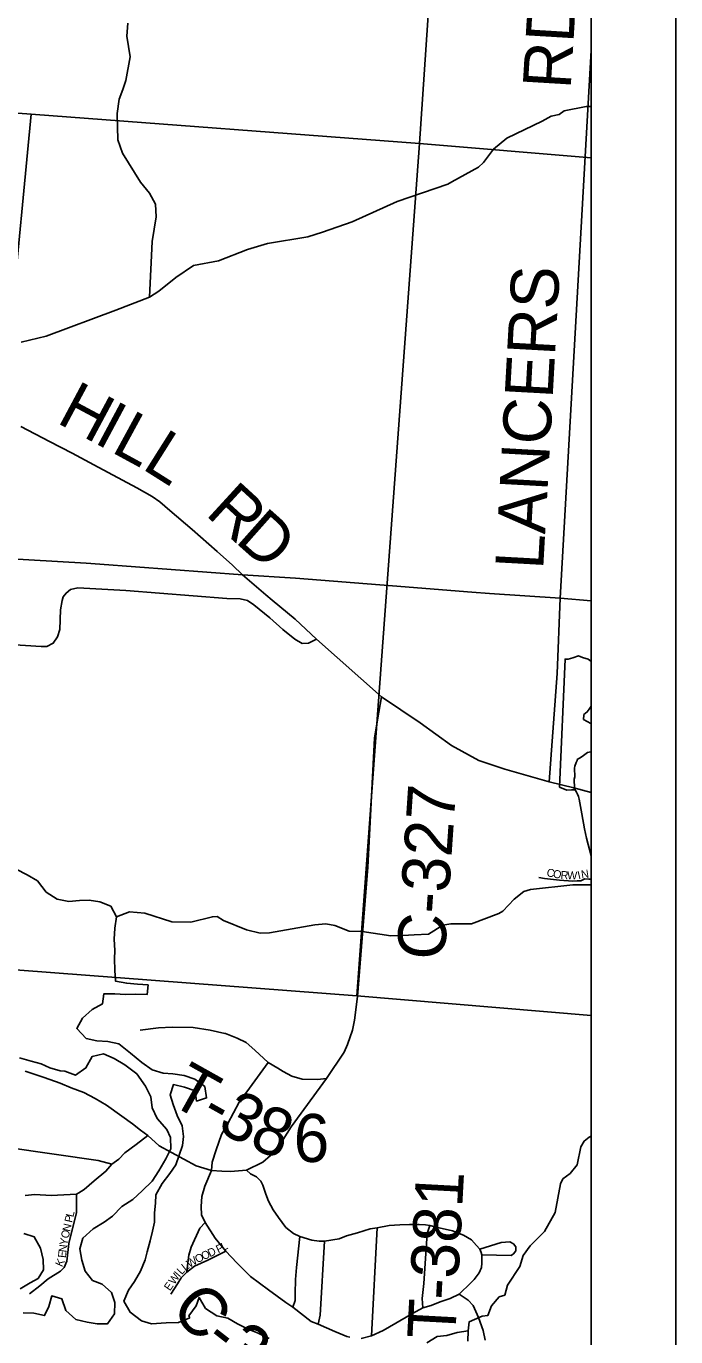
# Model space of a CAD drawing. Extents: x 0 to 40.4, y 0 to 22.
# Drawn here: x 8.731 to 9.5, y 15.17 to 16.72 of the extents above; entities that cross this region are included whole.
import ezdxf

# ---------------------------------------------------------------- set-up
doc = ezdxf.new("R2010")
doc.units = 0
for name, color, linetype in [('GM_X_County_Road', 7, 'Continuous'), ('GM_X_County_Road_Text', 7, 'Continuous'), ('GM_X_Interstate_Route', 7, 'Continuous'), ('GM_X_Major_Lake', 7, 'Continuous'), ('GM_X_Minor_Lake', 7, 'Continuous'), ('GM_X_Minor_River', 7, 'Continuous'), ('GM_X_Section', 7, 'Continuous'), ('GM_X_Township_Road', 7, 'Continuous'), ('GM_X_Township_Road_Text', 7, 'Continuous'), ('GM_X_Township_Subdivision', 7, 'Continuous'), ('GM_X_Township_Subdivision_Text', 7, 'Continuous'), ('SH_Data', 7, 'Continuous')]:
    doc.layers.add(name, color=color, linetype=linetype)

msp = doc.modelspace()

# ---------------------------------------------------------------- linework, layer by layer
at = {"layer": 'GM_X_County_Road'}
for points in [[(9.3501, 15.8263), (9.3597, 15.9545), (9.3632, 16.0434), (9.4, 16.6916)], [(8.725, 16.2467), (8.7589, 16.2289), (8.7858, 16.2152), (8.8114, 16.2014), (8.8624, 16.1742), (8.8803, 16.1638), (8.8894, 16.1574), (8.9013, 16.1472), (8.9275, 16.1249), (8.9571, 16.0988), (8.9755, 16.0824), (8.9871, 16.071), (9.0149, 16.0474), (9.0223, 16.0411), (9.0494, 16.0188), (9.0749, 15.9951), (9.1516, 15.9268), (9.1976, 15.8958), (9.2345, 15.869), (9.2671, 15.8514), (9.2977, 15.841), (9.3501, 15.8263), (9.3793, 15.819), (9.4, 15.8136)], [(9.1516, 15.9268), (9.147, 15.8996), (9.1436, 15.8778), (9.1356, 15.7253), (9.1233, 15.5721), (9.1197, 15.5443), (9.1173, 15.5324), (9.1114, 15.5153), (9.1076, 15.5061), (9.0865, 15.4753), (9.0448, 15.4181), (9.0307, 15.3953), (9.0208, 15.3841), (9.0205, 15.3839)], [(9.4, 15.7383), (9.3999, 15.7387), (9.3944, 15.7597), (9.3919, 15.7704), (9.3888, 15.7884), (9.3856, 15.8057), (9.3847, 15.8089), (9.3837, 15.8117), (9.3824, 15.8138), (9.3793, 15.819)], [(9.0205, 15.3839), (9.0114, 15.3762), (8.9919, 15.3667), (8.9731, 15.3652), (8.9629, 15.3654), (8.9506, 15.3662), (8.9324, 15.3717), (8.8886, 15.3954), (8.8754, 15.4076), (8.8667, 15.4141), (8.8571, 15.4215), (8.8445, 15.4307), (8.8262, 15.4434), (8.8129, 15.4515), (8.7996, 15.4585), (8.7845, 15.4641), (8.7714, 15.4695), (8.7525, 15.4765), (8.7302, 15.4837)], [(8.7302, 15.3367), (8.7415, 15.338), (8.761, 15.3368), (8.791, 15.3384), (8.7937, 15.3398), (8.7998, 15.3439), (8.8116, 15.3541), (8.8257, 15.3654), (8.8327, 15.3739), (8.841, 15.3798), (8.8482, 15.3871), (8.8614, 15.3969), (8.8754, 15.4076)], [(8.9506, 15.3662), (8.9426, 15.3478), (8.9391, 15.3354), (8.9382, 15.3236), (8.9388, 15.3137), (8.943, 15.3048), (8.9551, 15.2861), (8.9675, 15.2707), (8.9807, 15.2571), (8.9969, 15.241), (9.0181, 15.2249), (9.0385, 15.2101), (9.047, 15.2045), (9.0685, 15.1877), (9.0768, 15.1846), (9.0967, 15.1758), (9.1106, 15.1698), (9.1141, 15.1689)], [(9.1276, 15.1673), (9.1399, 15.1707), (9.1537, 15.177), (9.1886, 15.1972), (9.2007, 15.2037), (9.2106, 15.2066), (9.2212, 15.2108), (9.233, 15.2149), (9.2437, 15.2201), (9.2575, 15.2333), (9.2615, 15.2373), (9.2675, 15.2453), (9.2699, 15.2514), (9.2705, 15.2566), (9.2704, 15.2664), (9.2698, 15.2693), (9.2682, 15.2732), (9.2642, 15.2776), (9.2582, 15.2843), (9.2489, 15.2899), (9.2356, 15.2948), (9.2163, 15.2994), (9.2091, 15.3013), (9.204, 15.3021), (9.1963, 15.3022), (9.1849, 15.3023), (9.1733, 15.302), (9.161, 15.3011), (9.1465, 15.2985), (9.1382, 15.2971), (9.1234, 15.2927), (9.1103, 15.2888), (9.1018, 15.2855), (9.0842, 15.2828), (9.0779, 15.2828), (9.0692, 15.2837), (9.0551, 15.288), (9.0475, 15.2918), (9.0387, 15.2988), (9.0299, 15.3106), (9.0236, 15.3199), (9.0182, 15.33), (9.0148, 15.3382), (9.0113, 15.3491), (9.009, 15.3538), (9.0039, 15.3588), (8.9966, 15.3622), (8.9919, 15.3667)], [(9.2437, 15.2201), (9.2542, 15.213), (9.2604, 15.2065), (9.2665, 15.1924), (9.2719, 15.177), (9.2746, 15.1654)]]:
    msp.add_lwpolyline(points, dxfattribs=at)
at = {"layer": 'GM_X_Interstate_Route'}
for points in [[(7.7959, 16.068), (7.8971, 16.0785), (8.0522, 16.0948), (8.1652, 16.1082), (8.2508, 16.1101), (8.3578, 16.109), (8.7001, 16.0907), (8.8023, 16.0849), (8.8184, 16.0837)], [(8.8184, 16.0837), (8.9871, 16.071), (9.0501, 16.0671), (9.1647, 16.0579)], [(9.1647, 16.0579), (9.2585, 16.0504), (9.2796, 16.049)], [(9.2796, 16.049), (9.3632, 16.0434), (9.4, 16.0404)]]:
    msp.add_lwpolyline(points, dxfattribs=at)
at = {"layer": 'GM_X_Major_Lake'}
for points in [[(8.8756, 15.5859), (8.8628, 15.5868), (8.8503, 15.5879), (8.8371, 15.5903), (8.836, 15.6032), (8.8357, 15.6168), (8.8361, 15.6267), (8.8354, 15.64), (8.8362, 15.6532), (8.8382, 15.6665), (8.8314, 15.679), (8.8186, 15.684), (8.8057, 15.686), (8.7944, 15.6856), (8.7819, 15.6845), (8.7679, 15.6872), (8.7551, 15.6956), (8.7445, 15.7089), (8.7325, 15.7162), (8.7193, 15.7227)], [(8.9251, 15.1921), (8.9114, 15.1865), (8.8971, 15.1862), (8.8797, 15.1847), (8.8676, 15.1882), (8.8544, 15.1985), (8.8469, 15.2118), (8.8522, 15.2246), (8.8595, 15.2349), (8.8667, 15.247), (8.872, 15.2606), (8.8744, 15.2701), (8.8778, 15.2829), (8.8809, 15.2943), (8.8832, 15.3053), (8.8832, 15.3163), (8.8844, 15.3277), (8.8845, 15.3375), (8.8921, 15.3508), (8.9012, 15.3629), (8.9084, 15.3731), (8.9161, 15.3958), (8.9176, 15.4064), (8.9158, 15.4193), (8.9098, 15.4315), (8.9053, 15.4444), (8.9016, 15.4558), (8.9054, 15.4679), (8.9186, 15.4648), (8.9311, 15.4606), (8.9329, 15.4484), (8.9447, 15.4522), (8.9425, 15.4655), (8.9308, 15.4742), (8.9183, 15.4785), (8.9047, 15.4808), (8.8934, 15.4816), (8.8805, 15.4854), (8.8681, 15.4942), (8.8549, 15.5053), (8.8409, 15.5163), (8.8277, 15.519), (8.8149, 15.5198), (8.8024, 15.5225), (8.7911, 15.5343), (8.798, 15.5464), (8.8093, 15.5566), (8.8215, 15.5634), (8.823, 15.5752), (8.8363, 15.5755), (8.8487, 15.5747), (8.8608, 15.575), (8.8745, 15.5746), (8.8756, 15.5859)], [(8.7769, 15.4839), (8.7716, 15.4843), (8.7591, 15.4878), (8.749, 15.4924), (8.7372, 15.4955), (8.7233, 15.4997)], [(8.8686, 15.3421), (8.8804, 15.3538), (8.8884, 15.366), (8.8967, 15.38), (8.9025, 15.3921), (8.9021, 15.4053), (8.8976, 15.4148), (8.8863, 15.4278), (8.8803, 15.4403), (8.8789, 15.4536), (8.8725, 15.4661), (8.8624, 15.4806), (8.848, 15.4913), (8.8352, 15.4989), (8.8227, 15.5042), (8.8095, 15.5013), (8.8019, 15.4876), (8.7897, 15.479), (8.7769, 15.4839)], [(8.7277, 15.1978), (8.7402, 15.1974), (8.753, 15.1947), (8.758, 15.2053), (8.7615, 15.2178), (8.7735, 15.2143), (8.778, 15.2007), (8.7901, 15.19), (8.8033, 15.1869), (8.8154, 15.185), (8.8275, 15.1849), (8.8359, 15.1966), (8.8363, 15.2099), (8.8322, 15.2221), (8.8213, 15.2316), (8.8099, 15.2362), (8.8009, 15.2472), (8.7972, 15.2601), (8.7946, 15.2734), (8.7984, 15.2863), (8.8106, 15.2972), (8.8234, 15.3052), (8.8333, 15.3123), (8.8443, 15.3237), (8.8576, 15.3319), (8.8686, 15.3421)], [(8.7285, 15.2919), (8.7409, 15.2876), (8.7481, 15.2743), (8.7514, 15.2611), (8.7517, 15.2489), (8.7453, 15.2383), (8.7358, 15.2334), (8.724, 15.2263)], [(9.0188, 15.1675), (9.0059, 15.1736), (8.9939, 15.1786), (8.9814, 15.1847), (8.9697, 15.1916), (8.9569, 15.1943), (8.9433, 15.2031), (8.9358, 15.216), (8.9323, 15.2061), (8.9236, 15.1944), (8.9251, 15.1921)], [(9.254, 15.1643), (9.2544, 15.1764), (9.2411, 15.1746), (9.229, 15.1712), (9.2177, 15.1698), (9.2055, 15.1622)]]:
    msp.add_lwpolyline(points, dxfattribs=at)
at = {"layer": 'GM_X_Minor_Lake'}
for points in [[(9.4, 15.9687), (9.398, 15.9703), (9.3965, 15.9714), (9.3897, 15.9733), (9.3848, 15.9752), (9.3783, 15.973), (9.3727, 15.9715), (9.3689, 15.9715), (9.3625, 15.8198)], [(9.3907, 15.9001), (9.3911, 15.9051), (9.3911, 15.9058), (9.3952, 15.9089), (9.3975, 15.9123), (9.4, 15.9157)], [(9.4, 15.8949), (9.3994, 15.8952), (9.3907, 15.9001)], [(9.3625, 15.8198), (9.3712, 15.8164), (9.3765, 15.8167), (9.3799, 15.8167), (9.3803, 15.8186), (9.3799, 15.8292), (9.3807, 15.8319), (9.38, 15.8425), (9.3804, 15.8448), (9.3823, 15.849), (9.3834, 15.8516), (9.3834, 15.8524), (9.3879, 15.8554), (9.3906, 15.8573), (9.3955, 15.8607), (9.3993, 15.8618), (9.4, 15.8619)]]:
    msp.add_lwpolyline(points, dxfattribs=at)
at = {"layer": 'GM_X_Minor_River'}
for points in [[(8.8771, 16.3998), (8.8802, 16.4654), (8.8852, 16.4946), (8.8841, 16.5097), (8.8773, 16.5226), (8.8667, 16.5359), (8.8453, 16.5701), (8.8396, 16.586), (8.8389, 16.6171), (8.8412, 16.6338), (8.8458, 16.6455), (8.8492, 16.6562), (8.8542, 16.6842), (8.8504, 16.7085), (8.8516, 16.724)], [(8.7253, 16.3466), (8.7548, 16.3537), (8.8373, 16.3843), (8.8771, 16.3998), (8.8884, 16.4066), (8.9085, 16.4228), (8.9293, 16.4372), (8.9588, 16.4425), (8.9932, 16.4561), (9.0167, 16.4632), (9.0647, 16.4711), (9.0821, 16.4767), (9.117, 16.4888), (9.1703, 16.513), (9.2301, 16.5333), (9.235, 16.536), (9.2664, 16.5534), (9.2725, 16.559), (9.2842, 16.5749), (9.3001, 16.5878), (9.3418, 16.6078), (9.3527, 16.6139), (9.3618, 16.6157), (9.3679, 16.6203), (9.394, 16.6252), (9.4, 16.6252)], [(8.8382, 15.6665), (8.8537, 15.6725), (8.8715, 15.6706), (8.9036, 15.6606), (8.9263, 15.6602), (8.9516, 15.6666), (8.9573, 15.667), (8.9648, 15.662), (8.9921, 15.651), (9.0083, 15.6472), (9.0193, 15.6475), (9.073, 15.6569), (9.0858, 15.658), (9.0964, 15.6561), (9.1134, 15.6496), (9.1289, 15.6492), (9.1626, 15.6438), (9.1837, 15.6446), (9.1902, 15.6453), (9.2072, 15.646), (9.2242, 15.6566), (9.2337, 15.6581), (9.2582, 15.6581), (9.2904, 15.6705), (9.2953, 15.6732), (9.3086, 15.6872), (9.3203, 15.6963), (9.3279, 15.6989), (9.3782, 15.7041), (9.4, 15.7041)], [(9.2544, 15.1764), (9.2554, 15.1871), (9.271, 15.1939), (9.2774, 15.1946), (9.2819, 15.206), (9.291, 15.2166), (9.2975, 15.2189), (9.3009, 15.2306), (9.3153, 15.2526), (9.3195, 15.2655), (9.3278, 15.2772), (9.3369, 15.2863), (9.3445, 15.2942), (9.3574, 15.3166), (9.3635, 15.3503), (9.3662, 15.3564), (9.3749, 15.3628), (9.3832, 15.373), (9.3878, 15.3943), (9.3916, 15.4011), (9.3973, 15.4056), (9.4, 15.4069)]]:
    msp.add_lwpolyline(points, dxfattribs=at)
at = {"layer": 'GM_X_Section'}
for p, q in [((9.4, 16.5646), (9.4, 17.0997)), ((9.4, 15.5496), (9.4, 16.5646))]:
    msp.add_line(p, q, dxfattribs=at)
for points in [[(8.2373, 17.1912), (9.2326, 17.1127), (9.1966, 16.5816), (8.7372, 16.616), (8.202, 16.6562)], [(8.202, 16.6562), (8.7372, 16.616), (8.6406, 15.6095), (8.1289, 15.6484), (8.1953, 16.5941)], [(8.7372, 16.616), (9.1966, 16.5816), (9.1227, 15.573), (8.6406, 15.6095)]]:
    msp.add_lwpolyline(points, close=True, dxfattribs=at)
for points in [[(9.4, 17.0997), (9.2326, 17.1127), (9.1966, 16.5816), (9.4, 16.5646)], [(9.4, 16.5646), (9.1966, 16.5816), (9.1227, 15.573), (9.4, 15.5496)]]:
    msp.add_lwpolyline(points, dxfattribs=at)
at = {"layer": 'GM_X_Township_Road'}
for points in [[(9.0749, 15.9951), (9.0654, 15.9904), (9.058, 15.9898), (9.0492, 15.9948), (9.035, 16.0065), (9.0196, 16.0204), (9.0006, 16.0358), (8.993, 16.0407), (8.9844, 16.0426), (8.9686, 16.0432), (8.8491, 16.0525), (8.7924, 16.0557), (8.7837, 16.0537), (8.7784, 16.0496), (8.775, 16.0451), (8.7738, 16.0406), (8.7717, 16.0298), (8.7709, 16.0065), (8.7682, 15.9977), (8.7633, 15.9901), (8.7556, 15.9865), (8.749, 15.9863), (8.662, 15.9918)], [(8.8662, 15.5322), (8.8877, 15.5349), (8.904, 15.5358), (8.9287, 15.5356), (8.9491, 15.5322), (8.9663, 15.5285), (8.9671, 15.5282)], [(8.9671, 15.5282), (8.9808, 15.5228), (8.9917, 15.5178), (9.0019, 15.5087), (9.0175, 15.494), (9.0289, 15.4872), (9.0353, 15.4833), (9.0458, 15.4779), (9.0579, 15.4745), (9.076, 15.4741), (9.0865, 15.4753)], [(8.9506, 15.3662), (8.9512, 15.376), (8.9561, 15.3907), (8.9623, 15.4087), (8.9697, 15.4219), (8.9832, 15.4473), (8.9954, 15.4638), (9.0175, 15.494)], [(8.8327, 15.3739), (8.8163, 15.3781), (8.7096, 15.3935), (8.6678, 15.4005), (8.6653, 15.401)], [(9.1399, 15.1707), (9.1465, 15.2985)], [(9.2007, 15.2037), (9.1999, 15.2147), (9.2017, 15.2326), (9.2058, 15.2916), (9.2091, 15.3013)], [(9.047, 15.2045), (9.0497, 15.2126), (9.0497, 15.2208), (9.0499, 15.2374), (9.0513, 15.2513), (9.0551, 15.288)], [(9.0768, 15.1846), (9.0792, 15.1949), (9.0842, 15.2828)]]:
    msp.add_lwpolyline(points, dxfattribs=at)
at = {"layer": 'GM_X_Township_Subdivision'}
for points in [[(9.3379, 15.7129), (9.3447, 15.7117), (9.3622, 15.71), (9.378, 15.7087), (9.3834, 15.7091), (9.3877, 15.7091), (9.3922, 15.7115), (9.397, 15.711), (9.4, 15.7109)], [(8.7352, 15.2205), (8.7476, 15.23), (8.7572, 15.2381), (8.7718, 15.2472), (8.7762, 15.2516), (8.7792, 15.259), (8.7819, 15.28), (8.7907, 15.3164), (8.791, 15.3384)], [(8.9214, 15.2461), (8.9221, 15.2538), (8.9236, 15.2659), (8.9265, 15.2755), (8.9367, 15.2982), (8.943, 15.3048)], [(9.2704, 15.2664), (9.305, 15.2656), (9.3079, 15.2675), (9.3106, 15.2713), (9.3109, 15.2759), (9.3079, 15.2796), (9.3036, 15.2817), (9.2932, 15.2811), (9.2682, 15.2732)], [(8.9023, 15.2201), (8.9104, 15.2322), (8.9147, 15.2391), (8.9214, 15.2461), (8.9305, 15.2531), (8.9463, 15.2601), (8.9675, 15.2707)]]:
    msp.add_lwpolyline(points, dxfattribs=at)
at = {"layer": 'SH_Data'}
for p, q in [((9.5, 21), (9.5, 14)), ((9.4, 20.9), (9.4, 14.1))]:
    msp.add_line(p, q, dxfattribs=at)

# ---------------------------------------------------------------- texts
at = {"layer": 'GM_X_County_Road_Text'}
for s, height, rotation, p in [('RD', 0.05682, 86.5467, (9.3755, 16.6451)), ('LANCERS', 0.05682, 86.8369, (9.343, 16.0766)), ('H', 0.0568, 331.8594, (8.7658, 16.2518)), ('I', 0.0568, 331.8499, (8.8099, 16.2282)), ('L', 0.0568, 331.4682, (8.8304, 16.2172)), ('L', 0.0568, 327.7507, (8.8669, 16.1974)), ('R', 0.0568, 317.515, (8.9421, 16.1427)), ('D', 0.0568, 318.376, (8.9772, 16.1106)), ('C-327', 0.05682, 86.1501, (9.2263, 15.6142)), ('C', 0.0568, 314.8096, (8.9002, 15.1994)), ('3', 0.0568, 323.9091, (8.959, 15.1455)), ('-', 0.0568, 322.1082, (8.939, 15.161))]:
    msp.add_text(s, height=height, rotation=rotation, dxfattribs=at).set_placement(p)
at = {"layer": 'GM_X_Township_Road_Text'}
for s, height, rotation, p in [('T', 0.0568, 330.724, (8.8979, 15.4469)), ('-', 0.0568, 330.7854, (8.935, 15.4261)), ('3', 0.0568, 331.0548, (8.9556, 15.4146)), ('8', 0.0568, 338.106, (8.9932, 15.3943)), ('6', 0.0568, 358.6157, (9.0472, 15.3769)), ('T-381', 0.05682, 86.913, (9.2388, 15.1659))]:
    msp.add_text(s, height=height, rotation=rotation, dxfattribs=at).set_placement(p)
at = {"layer": 'GM_X_Township_Subdivision_Text'}
for s, rotation, p in [('C', 348.2614, (9.3465, 15.7147)), ('O', 349.6016, (9.3541, 15.7131)), ('R', 355.8787, (9.3634, 15.7114)), ('W', 358.179, (9.3713, 15.7109)), ('I', 13.4204, (9.3849, 15.7108)), ('N', 8.8442, (9.3887, 15.7117)), ('P', 77.1364, (8.7856, 15.304)), ('L', 77.7914, (8.7871, 15.3106)), ('O', 77.1938, (8.7813, 15.2853)), ('N', 77.1299, (8.7831, 15.2934)), ('N', 83.2518, (8.7789, 15.2691)), ('Y', 79.6932, (8.7798, 15.2772)), ('P', 25.2942, (8.9585, 15.2682)), ('L', 25.3186, (8.9645, 15.2711)), ('K', 64.6372, (8.7737, 15.2515)), ('E', 84.3499, (8.7782, 15.2625)), ('W', 30.7648, (8.9245, 15.2509)), ('O', 25.8807, (8.9337, 15.2564)), ('O', 25.3139, (8.9411, 15.26)), ('D', 25.2942, (8.9487, 15.2636)), ('W', 54.7105, (8.9066, 15.2306)), ('I', 50.0769, (8.9128, 15.2393)), ('L', 47.1068, (8.9153, 15.2424)), ('L', 38.5147, (8.9196, 15.247)), ('E', 54.7259, (8.9013, 15.2231))]:
    msp.add_text(s, height=0.00947, rotation=rotation, dxfattribs=at).set_placement(p)

doc.saveas('drawing.dxf')
